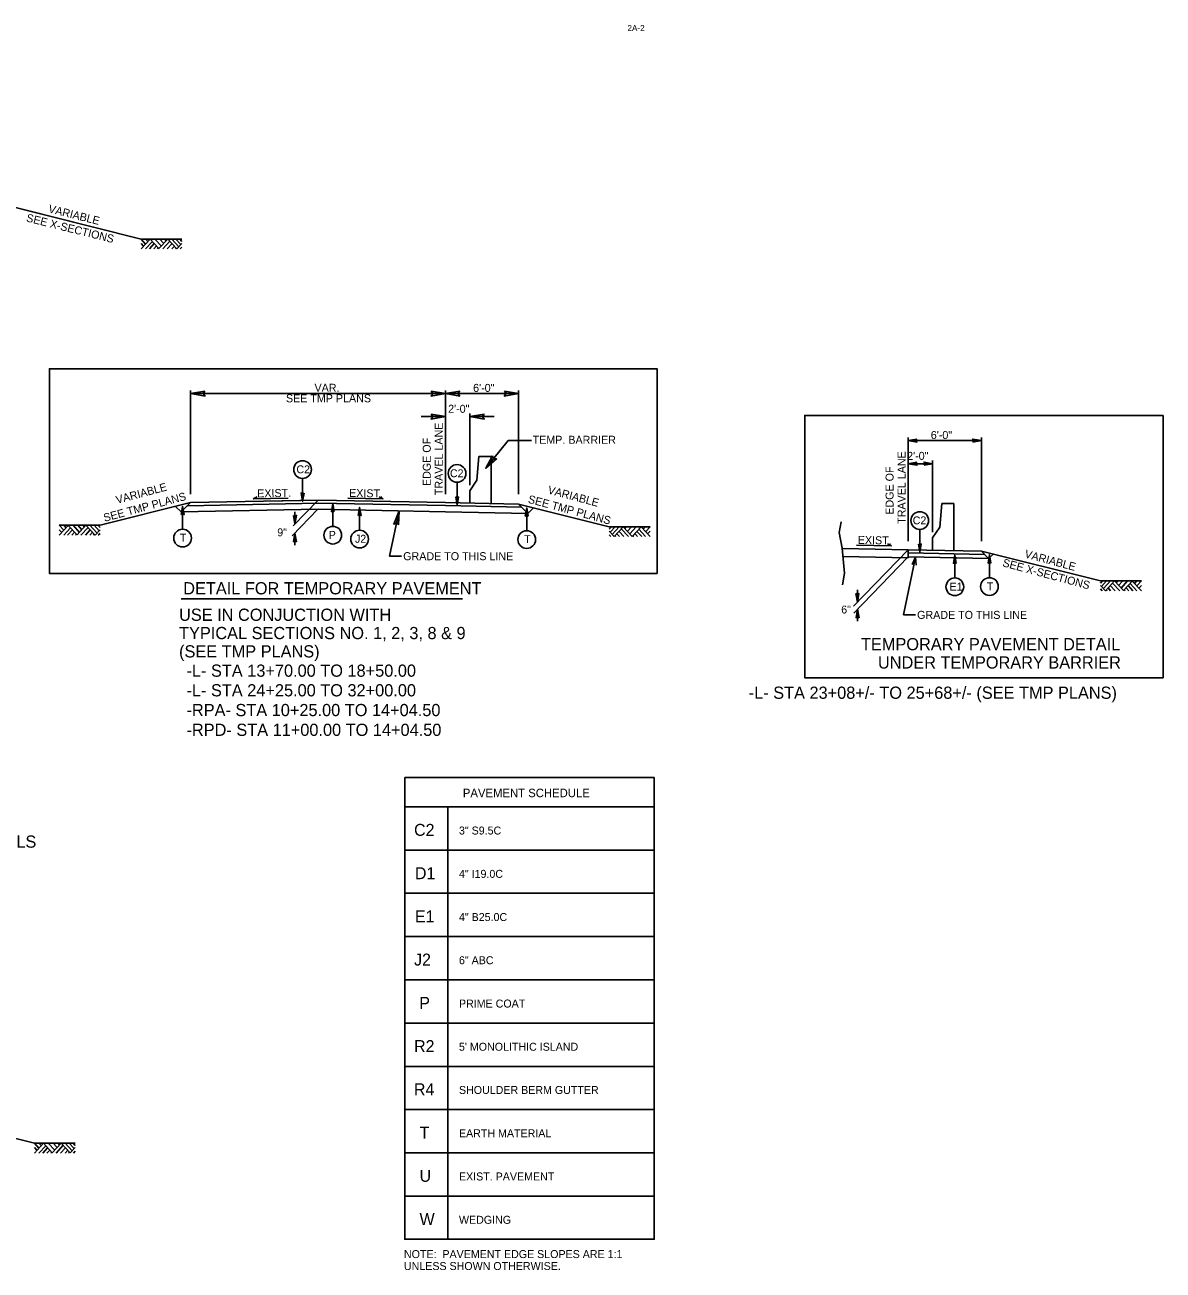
# Model space of a CAD drawing. Extents: x 1901582 to 1902252, y 193723 to 194156.
# Drawn here: x 1902078.1 to 1902171.4, y 193943.2 to 194045.2 of the extents above; entities that cross this region are included whole.
import ezdxf

# ---------------------------------------------------------------- set-up
doc = ezdxf.new("R2010")
doc.units = 0
for name, color, linetype in [('Old_Level_1', 7, 'Continuous'), ('Old_Level_11', 7, 'Continuous'), ('Old_Level_2', 7, 'Continuous'), ('Old_Level_20', 7, 'Continuous'), ('Old_Level_21', 7, 'Continuous'), ('Old_Level_44', 7, 'Continuous'), ('Prop Pavement Schedule Description CELL', 7, 'Continuous'), ('Typical Detail Wedge2 CELL', 7, 'Continuous'), ('Typical Median Barrier CELL', 7, 'Continuous'), ('Typical Terminator CELL', 7, 'Continuous')]:
    doc.layers.add(name, color=color, linetype=linetype)

# ---------------------------------------------------------------- blocks, each defined once
blk = doc.blocks.new('TERMINATOR')
at = {"layer": 'Typical Terminator CELL'}
blk.add_lwpolyline([(-0.469, 0.081), (0, 0), (-0.471, -0.083), (-0.411, 0)], close=True, dxfattribs=at)

msp = doc.modelspace()

# ---------------------------------------------------------------- linework, layer by layer
at = {"layer": 'Old_Level_1'}
for p, q in [((1902075.38, 194030.74), (1902083.38, 194028.74)), ((1902075.38, 194030.74), (1902087.62, 194027.67)), ((1902091.68, 194006.77), (1902091.68, 194015.27)), ((1902112.56, 194015.02), (1902091.68, 194015.02)), ((1902112.56, 194006.77), (1902112.56, 194015.27)), ((1902118.56, 194015.02), (1902112.56, 194015.02)), ((1902118.56, 194006.77), (1902118.56, 194015.27)), ((1902112.56, 194013.13), (1902110.56, 194013.13)), ((1902114.56, 194007.52), (1902114.56, 194013.39)), ((1902116.56, 194013.13), (1902114.56, 194013.13)), ((1902115.87, 194008.89), (1902117.7, 194011.18)), ((1902117.7, 194011.18), (1902119.61, 194011.18)), ((1902150.49, 194002.91), (1902150.49, 194011.41)), ((1902156.49, 194011.16), (1902150.49, 194011.16)), ((1902156.49, 194002.91), (1902156.49, 194011.41)), ((1902152.49, 194009.27), (1902150.49, 194009.27)), ((1902152.49, 194003.66), (1902152.49, 194009.53)), ((1902091.68, 194006.08), (1902084.25, 194004.22)), ((1902090.91, 194005.31), (1902090.45, 194005.77)), ((1902091.68, 194006.08), (1902090.91, 194005.31)), ((1902102.12, 194006.03), (1902091.42, 194005.82)), ((1902102.12, 194006.28), (1902091.68, 194006.08)), ((1902096.79, 194006.38), (1902097.12, 194006.55)), ((1902099.67, 194006.44), (1902096.79, 194006.38)), ((1902102.12, 194006.28), (1902097.84, 194006.2)), ((1902102.12, 194006.28), (1902100.07, 194004.17)), ((1902102.12, 194006.28), (1902112.56, 194006.08)), ((1902102.12, 194006.03), (1902112.56, 194005.83)), ((1902104.57, 194006.44), (1902107.45, 194006.38)), ((1902107.45, 194006.38), (1902107.12, 194006.55)), ((1902112.56, 194006.08), (1902118.56, 194005.96)), ((1902112.56, 194005.83), (1902118.81, 194005.7)), ((1902118.56, 194005.96), (1902119.32, 194005.19)), ((1902118.56, 194005.96), (1902125.99, 194004.1)), ((1902102.12, 194005.53), (1902090.91, 194005.31)), ((1902102.11, 194005.53), (1902100.01, 194003.36)), ((1902100.23, 194005.33), (1902100.23, 194004.33)), ((1902102.12, 194005.53), (1902112.56, 194005.33)), ((1902108.76, 194005.4), (1902107.98, 194001.7)), ((1902112.56, 194005.33), (1902119.32, 194005.19)), ((1902119.32, 194005.19), (1902119.78, 194005.65)), ((1902100.22, 194003.58), (1902100.22, 194002.58)), ((1902149.13, 194002.53), (1902148.8, 194002.7)), ((1902108.97, 194001.7), (1902107.98, 194001.7)), ((1902145.07, 194002.33), (1902150.49, 194002.22)), ((1902150.49, 194002.22), (1902146.01, 193997.59)), ((1902146.25, 194002.6), (1902149.13, 194002.53)), ((1902150.49, 194002.22), (1902150.49, 194001.64)), ((1902150.49, 194002.22), (1902156.49, 194002.1)), ((1902150.49, 194001.97), (1902156.74, 194001.84)), ((1902156.49, 194002.1), (1902157.08, 194001.5)), ((1902156.49, 194002.1), (1902166.25, 193999.66)), ((1902157.08, 194001.5), (1902157.44, 194001.86)), ((1902145.14, 194001.66), (1902150.48, 194001.55)), ((1902150.49, 194001.64), (1902146.02, 193997.02)), ((1902151.1, 194001.62), (1902150.11, 193996.88)), ((1902150.49, 194001.64), (1902150.48, 194001.55)), ((1902150.49, 194001.64), (1902157.08, 194001.5)), ((1902146.33, 193998.92), (1902146.33, 193997.92)), ((1902146.34, 193997.35), (1902146.34, 193996.35)), ((1902151.08, 193996.88), (1902150.11, 193996.88)), ((1902066.63, 193956.65), (1902078.87, 193953.59))]:
    msp.add_line(p, q, dxfattribs=at)
for points in [[(1902087.62, 194027.67), (1902090.96, 194027.67)], [(1902080.91, 194004.22), (1902084.25, 194004.22)], [(1902129.33, 194004.1), (1902125.99, 194004.1)], [(1902150.81, 194001.01), (1902151.1, 194001.62), (1902151.13, 194000.95)], [(1902169.6, 193999.66), (1902166.25, 193999.66)], [(1902078.87, 193953.59), (1902082.22, 193953.59)]]:
    msp.add_lwpolyline(points, dxfattribs=at)
msp.add_lwpolyline([(1902129.91, 194000.27), (1902080.11, 194000.27), (1902080.11, 194017.05), (1902129.91, 194017.05)], close=True, dxfattribs=at)
at = {"layer": 'Old_Level_11'}
for p, q in [((1902087.62, 194026.87), (1902088.36, 194027.67)), ((1902087.62, 194027.67), (1902087.99, 194027.27)), ((1902087.62, 194027.31), (1902087.82, 194027.09)), ((1902087.99, 194027.67), (1902088.18, 194027.47)), ((1902087.99, 194026.87), (1902088.55, 194027.47)), ((1902088.3, 194026.87), (1902088.7, 194027.3)), ((1902088.36, 194027.67), (1902089.08, 194026.89)), ((1902088.75, 194027.67), (1902089.28, 194027.1)), ((1902089.08, 194026.89), (1902089.82, 194027.67)), ((1902089.15, 194027.67), (1902089.48, 194027.32)), ((1902089.39, 194026.87), (1902089.98, 194027.5)), ((1902089.55, 194027.67), (1902089.68, 194027.53)), ((1902089.76, 194026.87), (1902090.16, 194027.3)), ((1902089.82, 194027.67), (1902090.56, 194026.88)), ((1902090.14, 194027.67), (1902090.72, 194027.05)), ((1902090.47, 194027.67), (1902090.88, 194027.23)), ((1902090.56, 194026.88), (1902090.96, 194027.31)), ((1902090.79, 194027.67), (1902090.96, 194027.49)), ((1902088.65, 194026.87), (1902088.88, 194027.11)), ((1902088.96, 194026.87), (1902089.03, 194026.95)), ((1902090.13, 194026.87), (1902090.35, 194027.1)), ((1902090.43, 194026.87), (1902090.49, 194026.94)), ((1902090.83, 194026.87), (1902090.96, 194027.01)), ((1902100.85, 194008.06), (1902100.85, 194006.19)), ((1902113.51, 194007.74), (1902113.51, 194005.87)), ((1902091.02, 194003.9), (1902091.02, 194005.77)), ((1902103.33, 194004.14), (1902103.33, 194006.01)), ((1902105.53, 194003.82), (1902105.53, 194005.69)), ((1902119.22, 194003.78), (1902119.22, 194005.65)), ((1902080.91, 194004.22), (1902081.28, 194003.81)), ((1902080.91, 194003.41), (1902081.65, 194004.21)), ((1902080.91, 194003.86), (1902081.11, 194003.63)), ((1902081.28, 194004.22), (1902081.47, 194004.02)), ((1902081.28, 194003.41), (1902081.83, 194004.01)), ((1902081.59, 194003.41), (1902081.99, 194003.84)), ((1902081.65, 194004.21), (1902082.37, 194003.43)), ((1902082.04, 194004.22), (1902082.57, 194003.64)), ((1902082.37, 194003.43), (1902083.1, 194004.22)), ((1902082.44, 194004.22), (1902082.77, 194003.86)), ((1902082.68, 194003.41), (1902083.27, 194004.04)), ((1902082.84, 194004.22), (1902082.97, 194004.07)), ((1902083.05, 194003.41), (1902083.45, 194003.84)), ((1902083.1, 194004.22), (1902083.84, 194003.42)), ((1902083.42, 194004.22), (1902084, 194003.59)), ((1902083.76, 194004.22), (1902084.17, 194003.77)), ((1902083.84, 194003.42), (1902084.25, 194003.86)), ((1902084.08, 194004.22), (1902084.25, 194004.03)), ((1902126.16, 194004.1), (1902125.99, 194003.91)), ((1902126.39, 194003.3), (1902125.99, 194003.74)), ((1902126.48, 194004.1), (1902126.07, 194003.65)), ((1902126.81, 194004.1), (1902126.23, 194003.47)), ((1902127.13, 194004.1), (1902126.39, 194003.3)), ((1902127.19, 194003.29), (1902126.79, 194003.72)), ((1902127.56, 194003.29), (1902126.97, 194003.92)), ((1902127.87, 194003.31), (1902127.13, 194004.1)), ((1902127.4, 194004.1), (1902127.27, 194003.95)), ((1902127.8, 194004.1), (1902127.47, 194003.74)), ((1902128.2, 194004.1), (1902127.67, 194003.52)), ((1902128.59, 194004.09), (1902127.87, 194003.31)), ((1902128.65, 194003.29), (1902128.25, 194003.72)), ((1902128.96, 194003.29), (1902128.4, 194003.89)), ((1902129.33, 194003.29), (1902128.59, 194004.09)), ((1902128.96, 194004.1), (1902128.77, 194003.9)), ((1902129.33, 194004.1), (1902128.96, 194003.69)), ((1902129.33, 194003.74), (1902129.13, 194003.51)), ((1902151.44, 194003.89), (1902151.44, 194002.01)), ((1902081.94, 194003.41), (1902082.16, 194003.66)), ((1902082.25, 194003.41), (1902082.32, 194003.49)), ((1902083.42, 194003.41), (1902083.63, 194003.65)), ((1902083.71, 194003.41), (1902083.78, 194003.49)), ((1902084.11, 194003.41), (1902084.25, 194003.56)), ((1902126.12, 194003.29), (1902125.99, 194003.44)), ((1902126.52, 194003.29), (1902126.46, 194003.37)), ((1902126.82, 194003.29), (1902126.6, 194003.53)), ((1902127.99, 194003.29), (1902127.92, 194003.37)), ((1902128.3, 194003.29), (1902128.07, 194003.54)), ((1902154.31, 193999.9), (1902154.31, 194001.78)), ((1902157.15, 193999.92), (1902157.15, 194001.8)), ((1902166.42, 193999.66), (1902166.25, 193999.47)), ((1902166.74, 193999.66), (1902166.33, 193999.21)), ((1902167.08, 193999.66), (1902166.5, 193999.03)), ((1902167.4, 193999.66), (1902166.66, 193998.86)), ((1902168.13, 193998.87), (1902167.4, 193999.66)), ((1902167.66, 193999.66), (1902167.53, 193999.51)), ((1902168.07, 193999.66), (1902167.73, 193999.3)), ((1902168.46, 193999.66), (1902167.93, 193999.08)), ((1902168.85, 193999.65), (1902168.13, 193998.87)), ((1902169.6, 193998.85), (1902168.85, 193999.65)), ((1902169.22, 193999.66), (1902169.03, 193999.46)), ((1902169.6, 193999.66), (1902169.22, 193999.25)), ((1902166.66, 193998.86), (1902166.25, 193999.3)), ((1902166.39, 193998.85), (1902166.25, 193999)), ((1902166.79, 193998.85), (1902166.72, 193998.93)), ((1902167.08, 193998.85), (1902166.87, 193999.09)), ((1902167.45, 193998.85), (1902167.05, 193999.28)), ((1902167.82, 193998.85), (1902167.23, 193999.48)), ((1902168.26, 193998.85), (1902168.18, 193998.93)), ((1902168.57, 193998.85), (1902168.34, 193999.1)), ((1902168.91, 193998.85), (1902168.51, 193999.28)), ((1902169.22, 193998.85), (1902168.67, 193999.45)), ((1902169.6, 193999.3), (1902169.39, 193999.07)), ((1902090.91, 193998.2), (1902113.95, 193998.2)), ((1902078.87, 193953.59), (1902079.25, 193953.18)), ((1902078.87, 193952.78), (1902079.62, 193953.58)), ((1902078.87, 193953.22), (1902079.08, 193953)), ((1902079.25, 193953.59), (1902079.44, 193953.39)), ((1902079.25, 193952.78), (1902079.8, 193953.38)), ((1902079.56, 193952.78), (1902079.96, 193953.21)), ((1902079.62, 193953.58), (1902080.34, 193952.8)), ((1902079.9, 193952.78), (1902080.13, 193953.02)), ((1902080.01, 193953.59), (1902080.54, 193953.01)), ((1902080.22, 193952.78), (1902080.29, 193952.86)), ((1902080.34, 193952.8), (1902081.07, 193953.59)), ((1902080.41, 193953.59), (1902080.74, 193953.23)), ((1902080.65, 193952.78), (1902081.24, 193953.41)), ((1902080.81, 193953.59), (1902080.94, 193953.44)), ((1902081.02, 193952.78), (1902081.42, 193953.21)), ((1902081.07, 193953.59), (1902081.81, 193952.79)), ((1902081.39, 193953.59), (1902081.97, 193952.96)), ((1902081.39, 193952.78), (1902081.6, 193953.01)), ((1902081.68, 193952.78), (1902081.75, 193952.86)), ((1902081.73, 193953.59), (1902082.14, 193953.14)), ((1902081.81, 193952.79), (1902082.22, 193953.22)), ((1902082.05, 193953.59), (1902082.22, 193953.4)), ((1902082.08, 193952.78), (1902082.22, 193952.92))]:
    msp.add_line(p, q, dxfattribs=at)
for points in [[(1902171.38, 194013.22), (1902142.01, 194013.22), (1902142.01, 193991.73), (1902171.38, 193991.73)], [(1902100.97, 194006.86), (1902100.85, 194006.19), (1902100.73, 194006.87), (1902100.85, 194006.78)], [(1902090.9, 194005.1), (1902091.02, 194005.77), (1902091.14, 194005.1), (1902091.02, 194005.18)], [(1902103.45, 194005.34), (1902103.33, 194006.01), (1902103.21, 194005.34), (1902103.33, 194005.42)], [(1902113.4, 194006.54), (1902113.51, 194005.87), (1902113.63, 194006.54), (1902113.51, 194006.46)], [(1902105.41, 194005.02), (1902105.53, 194005.69), (1902105.65, 194005.02), (1902105.53, 194005.1)], [(1902119.33, 194004.98), (1902119.22, 194005.65), (1902119.1, 194004.98), (1902119.22, 194005.06)], [(1902151.33, 194002.68), (1902151.44, 194002.01), (1902151.56, 194002.69), (1902151.44, 194002.6)], [(1902154.43, 194001.1), (1902154.31, 194001.78), (1902154.19, 194001.1), (1902154.31, 194001.19)], [(1902157.26, 194001.12), (1902157.15, 194001.8), (1902157.03, 194001.12), (1902157.15, 194001.21)]]:
    msp.add_lwpolyline(points, close=True, dxfattribs=at)
for centre in [(1902100.85, 194008.79), (1902113.51, 194008.47), (1902151.44, 194004.61), (1902091.02, 194003.17), (1902103.33, 194003.41), (1902105.53, 194003.09), (1902119.22, 194003.05), (1902154.31, 193999.18), (1902157.15, 193999.2)]:
    msp.add_circle(centre, 0.725, dxfattribs=at)
at = {"layer": 'Prop Pavement Schedule Description CELL'}
msp.add_lwpolyline([(1902109.22, 193983.55), (1902129.68, 193983.55), (1902129.68, 193981.14), (1902109.22, 193981.14)], close=True, dxfattribs=at)
for points in [[(1902112.76, 193977.6), (1902109.22, 193977.6), (1902109.22, 193981.14), (1902129.68, 193981.14), (1902129.68, 193977.6), (1902112.76, 193977.6), (1902112.76, 193981.14)], [(1902112.76, 193974.06), (1902109.22, 193974.06), (1902109.22, 193977.6), (1902129.68, 193977.6), (1902129.68, 193974.06), (1902112.76, 193974.06), (1902112.76, 193977.6)], [(1902112.76, 193970.51), (1902109.22, 193970.51), (1902109.22, 193974.06), (1902129.68, 193974.06), (1902129.68, 193970.51), (1902112.76, 193970.51), (1902112.76, 193974.06)], [(1902112.76, 193966.97), (1902109.22, 193966.97), (1902109.22, 193970.51), (1902129.68, 193970.51), (1902129.68, 193966.97), (1902112.76, 193966.97), (1902112.76, 193970.51)], [(1902112.76, 193963.43), (1902109.22, 193963.43), (1902109.22, 193966.97), (1902129.68, 193966.97), (1902129.68, 193963.43), (1902112.76, 193963.43), (1902112.76, 193966.97)], [(1902112.76, 193959.88), (1902109.22, 193959.88), (1902109.22, 193963.43), (1902129.68, 193963.43), (1902129.68, 193959.88), (1902112.76, 193959.88), (1902112.76, 193963.43)], [(1902112.76, 193956.34), (1902109.22, 193956.34), (1902109.22, 193959.88), (1902129.68, 193959.88), (1902129.68, 193956.34), (1902112.76, 193956.34), (1902112.76, 193959.88)], [(1902112.76, 193952.79), (1902109.22, 193952.79), (1902109.22, 193956.34), (1902129.68, 193956.34), (1902129.68, 193952.79), (1902112.76, 193952.79), (1902112.76, 193956.34)], [(1902112.76, 193949.25), (1902109.22, 193949.25), (1902109.22, 193952.79), (1902129.68, 193952.79), (1902129.68, 193949.25), (1902112.76, 193949.25), (1902112.76, 193952.79)], [(1902112.76, 193945.71), (1902109.22, 193945.71), (1902109.22, 193949.25), (1902129.68, 193949.25), (1902129.68, 193945.71), (1902112.76, 193945.71), (1902112.76, 193949.25)]]:
    msp.add_lwpolyline(points, dxfattribs=at)
at = {"layer": 'Typical Detail Wedge2 CELL'}
msp.add_lwpolyline([(1902144.99, 194004.51), (1902144.82, 194003.62), (1902145.07, 194002.35), (1902145.28, 194000.3), (1902145.11, 193999.33)], dxfattribs=at)
at = {"layer": 'Typical Median Barrier CELL'}
for p, q in [((1902115.31, 194009.87), (1902115.14, 194007.92)), ((1902115.81, 194009.87), (1902115.31, 194009.87)), ((1902115.81, 194009.87), (1902116.31, 194009.87)), ((1902116.31, 194009.87), (1902116.31, 194006.01)), ((1902115.14, 194007.92), (1902114.56, 194007.04)), ((1902114.56, 194007.04), (1902114.56, 194006.04)), ((1902153.24, 194006.01), (1902153.07, 194004.06)), ((1902153.74, 194006.01), (1902153.24, 194006.01)), ((1902153.74, 194006.01), (1902154.24, 194006.01)), ((1902154.24, 194006.01), (1902154.24, 194002.15)), ((1902153.07, 194004.06), (1902152.49, 194003.18)), ((1902152.49, 194003.18), (1902152.49, 194002.18))]:
    msp.add_line(p, q, dxfattribs=at)
at = {"layer": 'Typical Terminator CELL'}
for points in [[(1902092.85, 194015.22), (1902091.68, 194015.02), (1902092.86, 194014.81), (1902092.71, 194015.02)], [(1902111.39, 194015.22), (1902112.56, 194015.02), (1902111.38, 194014.81), (1902111.53, 194015.02)], [(1902113.73, 194015.22), (1902112.56, 194015.02), (1902113.74, 194014.81), (1902113.59, 194015.02)], [(1902117.39, 194015.22), (1902118.56, 194015.02), (1902117.38, 194014.81), (1902117.53, 194015.02)], [(1902111.39, 194013.33), (1902112.56, 194013.13), (1902111.38, 194012.92), (1902111.53, 194013.13)], [(1902115.73, 194013.33), (1902114.56, 194013.13), (1902115.74, 194012.92), (1902115.59, 194013.13)], [(1902116.43, 194009.91), (1902115.87, 194008.89), (1902116.75, 194009.66), (1902116.5, 194009.67)], [(1902108.72, 194004.25), (1902108.76, 194005.4), (1902108.32, 194004.32), (1902108.55, 194004.42)]]:
    msp.add_lwpolyline(points, close=True, dxfattribs=at)

# ---------------------------------------------------------------- block references
at = {"layer": 'Old_Level_1', "xscale": 1.5, "yscale": -1.5}
for p, rotation in [((1902150.49, 194011.16), 180), ((1902150.49, 194009.27), 180), ((1902100.23, 194004.33), -90), ((1902100.22, 194003.58), 90), ((1902146.33, 193997.92), -90), ((1902146.34, 193997.35), 90)]:
    msp.add_blockref('TERMINATOR', p, dxfattribs=dict(at, rotation=rotation))
for p in [(1902156.49, 194011.16), (1902152.49, 194009.27)]:
    msp.add_blockref('TERMINATOR', p, dxfattribs=at)

# ---------------------------------------------------------------- texts
at = {"layer": 'Old_Level_1'}
for s, rotation, p in [('VARIABLE', 345.9638, (1902079.97, 194029.87)), ('SEE X-SECTIONS', 345.9638, (1902078.16, 194029.13)), ('TRAVEL LANE', 90, (1902112.34, 194006.69)), ('EDGE OF', 90, (1902111.36, 194007.44)), ('TRAVEL LANE', 90, (1902150.27, 194004.34)), ('EDGE OF', 90, (1902149.29, 194005.09)), ('SEE TMP PLANS', 15.042, (1902084.63, 194004.5)), ('VARIABLE', 15.042, (1902085.65, 194005.97)), ('VARIABLE', 344.958, (1902120.9, 194006.84)), ('SEE TMP PLANS', 344.958, (1902119.28, 194006.08)), ('VARIABLE', 344.958, (1902159.98, 194001.59)), ('SEE X-SECTIONS', 344.958, (1902158.17, 194000.87))]:
    msp.add_text(s, height=0.656, rotation=rotation, dxfattribs=at).set_placement(p)
for s, p in [('SEE TMP PLANS', (1902099.49, 194014.3)), ('VAR.', (1902101.83, 194015.16)), ('6\'-0"', (1902114.83, 194015.15)), ('2\'-0"', (1902112.78, 194013.44)), ('6\'-0"', (1902152.34, 194011.29)), ('TEMP. BARRIER', (1902119.71, 194010.9)), ('2\'-0"', (1902150.4, 194009.58)), ('GRADE TO THIS LINE', (1902109.1, 194001.36)), ('GRADE TO THIS LINE', (1902151.22, 193996.55))]:
    msp.add_text(s, height=0.656, dxfattribs=at).set_placement(p)
at = {"layer": 'Old_Level_11'}
for s, p in [('DETAIL FOR TEMPORARY PAVEMENT', (1902091.07, 193998.56)), ('USE IN CONJUCTION WITH', (1902090.73, 193996.39)), ('TYPICAL SECTIONS NO. 1, 2, 3, 8 & 9', (1902090.73, 193994.89)), ('TEMPORARY PAVEMENT DETAIL ', (1902146.62, 193993.98)), ('(SEE TMP PLANS)', (1902090.73, 193993.39)), ('-L- STA 13+70.00 TO 18+50.00', (1902091.34, 193991.81)), ('UNDER TEMPORARY BARRIER', (1902148.01, 193992.48)), ('-L- STA 24+25.00 TO 32+00.00', (1902091.34, 193990.2)), ('-L- STA 23+08+/- TO 25+68+/- (SEE TMP PLANS)', (1902137.42, 193990)), ('-RPA- STA 10+25.00 TO 14+04.50', (1902091.34, 193988.58)), ('-RPD- STA 11+00.00 TO 14+04.50', (1902091.34, 193986.96)), ('SEE STRUCTURE PLANS FOR STRUCTURE CONSTRUCTION DETAILS', (1902034.08, 193977.8))]:
    msp.add_text(s, height=1, dxfattribs=at).set_placement(p)
at = {"layer": 'Old_Level_2'}
for rotation, p in [(1.1916, (1902097.14, 194006.5)), (358.8084, (1902104.66, 194006.55)), (358.8084, (1902146.35, 194002.7))]:
    msp.add_text('EXIST.', height=0.656, rotation=rotation, dxfattribs=at).set_placement(p)
at = {"layer": 'Old_Level_20'}
for s, p in [('C2', (1902100.35, 194008.48)), ('C2', (1902112.93, 194008.16)), ('C2', (1902150.86, 194004.3)), ('9"', (1902098.78, 194003.32)), ('P', (1902103, 194003.11)), ('T', (1902090.79, 194002.88)), ('J2', (1902105.15, 194002.79)), ('T', (1902119.01, 194002.76)), ('E1', (1902153.88, 193998.87)), ('T', (1902156.94, 193998.9)), ('6"', (1902145, 193996.99))]:
    msp.add_text(s, height=0.649, dxfattribs=at).set_placement(p)
at = {"layer": 'Old_Level_21'}
for s, height, p in [('C2', 0.98, (1902109.99, 193978.77)), ('3" S9.5C', 0.653, (1902113.67, 193978.88)), ('D1', 0.98, (1902110.06, 193975.22)), ('4" I19.0C', 0.653, (1902113.67, 193975.33)), ('E1', 0.98, (1902110.06, 193971.68)), ('4" B25.0C', 0.653, (1902113.67, 193971.79)), ('J2', 0.98, (1902109.99, 193968.14)), ('6" ABC', 0.653, (1902113.67, 193968.25)), ('P', 0.98, (1902110.42, 193964.59)), ('PRIME COAT', 0.653, (1902113.67, 193964.7)), ('R2', 0.98, (1902109.99, 193961.05)), ("5' MONOLITHIC ISLAND", 0.653, (1902113.67, 193961.16)), ('R4', 0.98, (1902109.98, 193957.51)), ('SHOULDER BERM GUTTER', 0.653, (1902113.67, 193957.62)), ('T', 0.98, (1902110.44, 193953.96)), ('EARTH MATERIAL', 0.653, (1902113.67, 193954.07)), ('U', 0.98, (1902110.44, 193950.42)), ('EXIST. PAVEMENT', 0.653, (1902113.67, 193950.53)), ('W', 0.98, (1902110.44, 193946.87)), ('WEDGING', 0.653, (1902113.67, 193946.98)), ('NOTE:  PAVEMENT EDGE SLOPES ARE 1:1', 0.653, (1902109.16, 193944.17)), ('UNLESS SHOWN OTHERWISE.', 0.653, (1902109.16, 193943.19))]:
    msp.add_text(s, height=height, dxfattribs=at).set_placement(p)
at = {"layer": 'Old_Level_44'}
msp.add_text('2A-2', height=0.5, dxfattribs=at).set_placement((1902127.48, 194044.72))
at = {"layer": 'Prop Pavement Schedule Description CELL'}
msp.add_text('PAVEMENT SCHEDULE', height=0.693, dxfattribs=at).set_placement((1902113.99, 193981.94))

doc.saveas('drawing.dxf')
